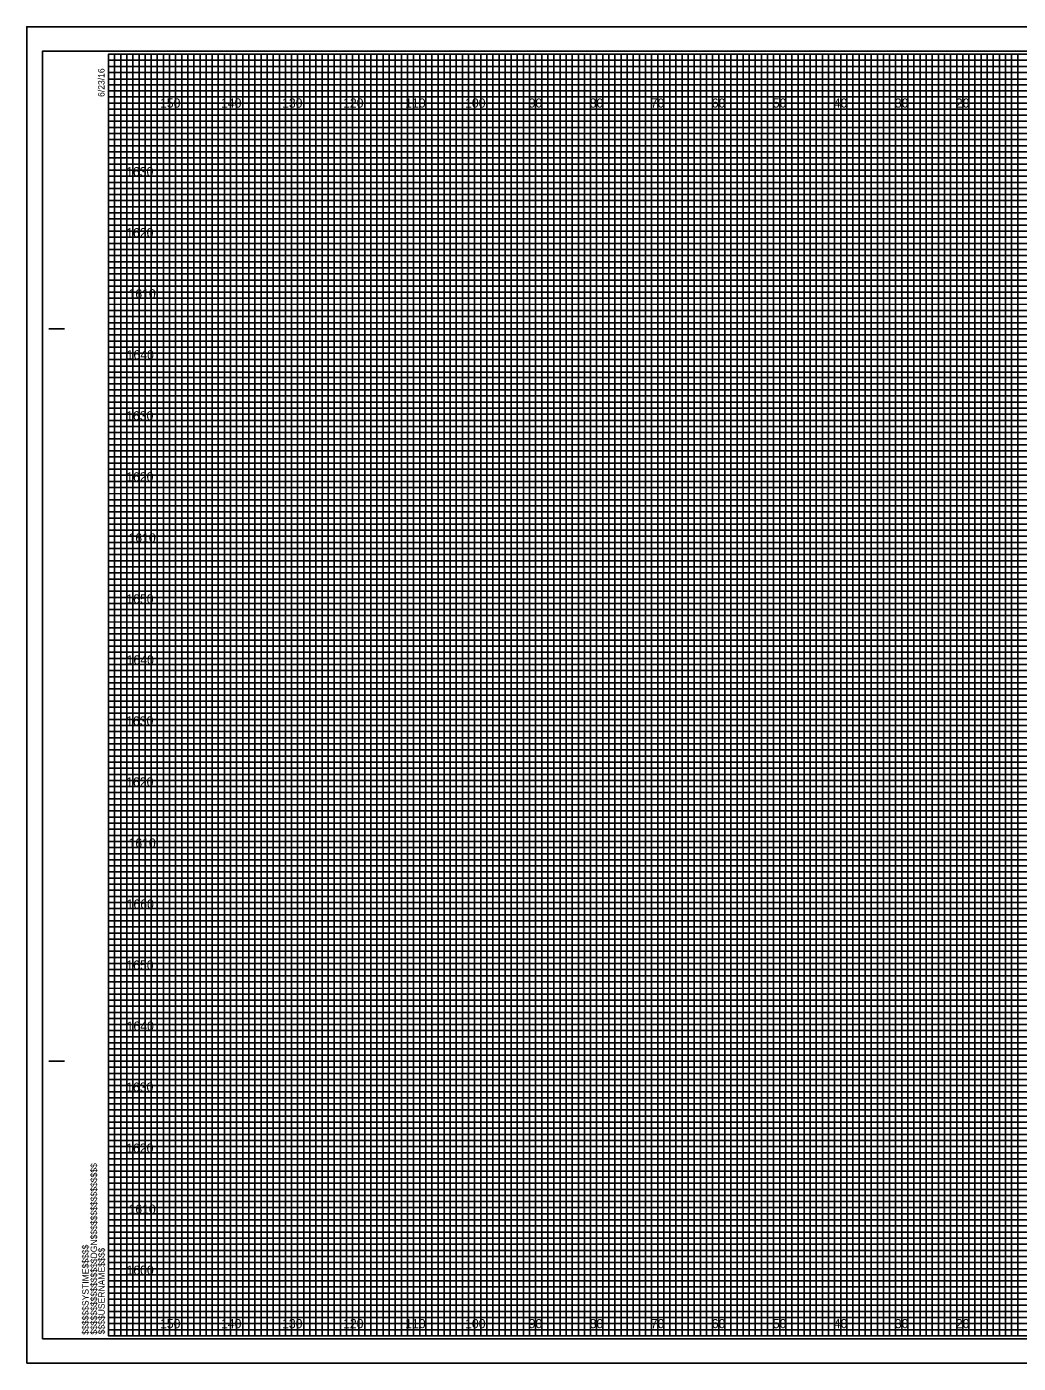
# Model space of a CAD drawing. Extents: x -13 to 323, y -5 to 6154.
# Drawn here: x -13.4 to 149.1, y 5935.5 to 6154.5 of the extents above; entities that cross this region are included whole.
import ezdxf

# ---------------------------------------------------------------- set-up
doc = ezdxf.new("R2010")
doc.units = 0
for name, color, linetype in [('Prop Retaining Wall', 7, 'Continuous'), ('Prop XS Alignment Label', 7, 'Continuous'), ('Prop XS DDE', 7, 'Continuous'), ('Prop XS DDE Elevations', 7, 'Continuous'), ('Prop XS DDE Slope Text', 7, 'Continuous'), ('Prop XS Earthwork Shape', 7, 'Continuous'), ('Prop XS Elevation Labels', 7, 'Continuous'), ('Prop XS Station Labels', 7, 'Continuous'), ('Raster_Level_0', 7, 'Continuous'), ('Scratch_Level_3', 7, 'Continuous'), ('Sheet Cutting Line CELL', 7, 'Continuous')]:
    doc.layers.add(name, color=color, linetype=linetype)

msp = doc.modelspace()

# ---------------------------------------------------------------- linework, layer by layer
at = {"layer": 'Prop Retaining Wall'}
for p, q in [((0, 6149), (260, 6149)), ((260, 6147.98), (0, 6147.98)), ((0, 6147.98), (0, 6147)), ((0, 6147), (260, 6147)), ((260, 6145.89), (0, 6145.89)), ((0, 6145.89), (0, 6144)), ((0, 6144), (320, 6144))]:
    msp.add_line(p, q, dxfattribs=at)
for points in [[(0, 6143), (270, 6143), (320, 6143), (320, 6142), (0, 6142)], [(0, 6141), (320, 6141), (320, 6139), (0, 6139)], [(0, 6138), (320, 6138), (320, 6137), (0, 6136.98)], [(0, 6136), (320, 6136), (320, 6134), (0, 6134)], [(0, 6133), (320, 6133), (320, 6132), (0, 6132)], [(0, 6131), (320, 6131), (320, 6129), (0, 6129)], [(0, 6128), (320, 6128), (320, 6127), (0, 6127)], [(0, 6126), (320, 6126), (320, 6124), (0, 6124)], [(0, 6123), (320, 6123), (320, 6122), (0, 6122)], [(0, 6121), (320, 6121), (320, 6119), (0, 6119)], [(0, 6118), (320, 6118), (320, 6117), (0, 6117)], [(0, 6116), (320, 6116), (320, 6113.95), (320, 6113), (320, 6112), (0, 6112)], [(0, 6114), (320, 6114), (320, 6113), (0, 6113)], [(0, 6111), (320, 6111), (320, 6109), (0, 6109.03)], [(0, 6109.03), (320, 6109), (320, 6108), (0, 6108)], [(0, 6107), (320, 6107), (320, 6106), (0, 6106)], [(0, 6104), (320, 6104), (320, 6103), (0, 6103)], [(0, 6102), (320, 6102), (320, 6101), (0, 6101)], [(-0.07, 6098.89), (320, 6098.89), (320, 6097.88), (-0.07, 6097.88)], [(0, 6097), (320, 6097), (320, 6096), (0, 6096)], [(0, 6094), (320, 6094), (320, 6093), (0, 6093)], [(0, 6092), (320, 6092), (320, 6091), (0, 6091)], [(0, 6089), (320, 6089), (320, 6088), (0, 6088)], [(0, 6087), (320, 6087), (320, 6086), (0, 6086)], [(0, 6084), (320, 6084), (320, 6083), (0, 6083)], [(0, 6082), (320, 6082), (320, 6081), (0, 6081)], [(0, 6079), (320, 6079), (319.99, 6077.98), (0, 6078)], [(0, 6077), (320, 6077), (320, 6076), (0, 6076)], [(0, 6074), (320, 6074), (320, 6073), (0, 6073)], [(0, 6072), (320, 6072), (320, 6071), (0, 6071)], [(0, 6069), (320, 6069), (320, 6068), (0, 6068)], [(0, 6067), (320, 6067), (320, 6066), (0, 6066)], [(0, 6064), (320, 6064), (320, 6063), (0, 6063)], [(0, 6062), (320, 6062), (320, 6061), (0, 6061)], [(0, 6059), (320, 6059), (320, 6058), (0, 6058)], [(0, 6056.99), (320.07, 6056.91), (320, 6056), (0, 6056)], [(0, 6054), (320, 6054), (320, 6053), (0, 6053)], [(0, 6052), (320, 6052), (320, 6051), (0, 6051)], [(0, 6049), (320, 6049), (320, 6048), (0, 6048)], [(0, 6047), (320, 6047), (320, 6046), (0, 6046)], [(0, 6044), (320, 6044), (320, 6043), (0, 6043)], [(0, 6042), (320, 6042), (320, 6041), (0, 6041)], [(0, 6039), (320, 6039), (320, 6038), (0, 6038)], [(0, 6037), (320, 6037), (320, 6036), (0, 6036)], [(0, 6034), (320, 6034), (320, 6033), (0, 6033)], [(0, 6032), (320, 6032), (320, 6031), (0, 6031)], [(0, 6029), (320, 6029), (320, 6028), (0, 6028)], [(0, 6027), (320, 6027), (320, 6026), (0, 6026)], [(0, 6024), (320, 6024), (320, 6023), (0, 6023)], [(0, 6022), (320, 6022), (320, 6021), (0, 6021)], [(0, 6019), (320, 6019), (319.99, 6017.98), (0, 6018)], [(0, 6017), (320, 6017), (320, 6016), (0, 6016)], [(0, 6014), (320, 6014), (320, 6013), (0, 6013)], [(0, 6012), (320, 6012), (320, 6011), (0, 6011)], [(0, 6009), (320, 6009), (320, 6008), (0, 6008)], [(0, 6007), (320, 6007), (320, 6006), (0, 6006)], [(0, 6004), (320, 6004), (320, 6003), (0, 6003)], [(0, 6002), (320, 6002), (320, 6001), (0, 6001)], [(0, 5999), (320, 5999), (320, 5998), (0, 5998)], [(0, 5996.99), (320.07, 5996.91), (320, 5996), (0, 5996)], [(0, 5994), (320, 5994), (320, 5993), (0, 5993)], [(0, 5992), (320, 5992), (320, 5991), (0, 5991)], [(0, 5989), (320, 5989), (320, 5988), (0, 5988)], [(0, 5987), (320, 5987), (320, 5986), (0, 5986)], [(0, 5984), (320, 5984), (320, 5983), (0, 5983)], [(0, 5982), (320, 5982), (320, 5981), (0, 5981)], [(0, 5979), (320, 5979), (320, 5978), (0, 5978)], [(0, 5977), (320, 5977), (320, 5976), (0, 5976)], [(0, 5974), (320, 5974), (320, 5973), (0, 5973)], [(0, 5972), (320, 5972), (320, 5971), (0, 5971)], [(0, 5969), (320, 5969), (320, 5968), (0, 5968)], [(0, 5967), (320, 5967), (320, 5966), (0, 5966)], [(0, 5964), (320, 5964), (320, 5963), (0, 5963)], [(0, 5962), (320, 5962), (320, 5961), (0, 5961)], [(0, 5959), (320, 5959), (320, 5958), (0, 5958)], [(0, 5957), (320, 5957), (320, 5956), (0, 5956)], [(0, 5954), (320, 5954), (320, 5953), (0, 5953)], [(0, 5952), (320, 5952), (320, 5951), (0, 5951)], [(0, 5949), (320, 5949), (320, 5948), (0, 5948)], [(0, 5947), (320, 5947), (320, 5946), (0, 5946)], [(0, 5944), (320, 5944), (320, 5943), (0, 5943)], [(0, 5942), (320, 5942), (320, 5941), (0, 5941)]]:
    msp.add_lwpolyline(points, dxfattribs=at)
at = {"layer": 'Prop XS Alignment Label'}
for p, q in [((-9.8, 6105), (-7.3, 6105)), ((-9.7, 6105), (-7.2, 6105)), ((-9.8, 5985), (-7.3, 5985)), ((-9.7, 5985), (-7.2, 5985)), ((0, 5940), (0, 5940)), ((0, 5940), (0, 5940)), ((0, 5940), (0, 5940)), ((0, 5940), (0, 5940)), ((0, 5940), (0, 5940)), ((0, 5940), (0, 5940)), ((0, 5940), (0, 5940))]:
    msp.add_line(p, q, dxfattribs=at)
msp.add_lwpolyline([(320, 6150), (0, 6150), (0, 5940), (320, 5940)], close=True, dxfattribs=at)
at = {"layer": 'Prop XS DDE'}
msp.add_lwpolyline([(-13.4, 5935.5), (323.3, 5935.5), (323.3, 6154.5), (-13.4, 6154.5)], close=True, dxfattribs=at)
at = {"layer": 'Prop XS DDE Elevations'}
for p, q in [((10, 5940), (10, 6150)), ((20, 5940), (20, 6150)), ((30, 5940), (30, 6150)), ((40, 5940), (40, 6150)), ((50, 5940), (50, 6150)), ((60, 5940), (60, 6150)), ((70, 5940), (70, 6150)), ((80, 5940), (80, 6150)), ((90, 5940), (90, 6150)), ((100, 5940), (100, 6150)), ((110, 5940), (110, 6150)), ((120, 5940), (120, 6150)), ((130, 5940), (130, 6150)), ((140, 5940), (140, 6150)), ((0, 6140), (320, 6140)), ((0, 6130), (320, 6130)), ((0, 6120), (320, 6120)), ((0, 6110), (320, 6110)), ((0, 6100), (320, 6100)), ((0, 6090), (320, 6090)), ((0, 6080), (320, 6080)), ((0, 6070), (320, 6070)), ((0, 6060), (320, 6060)), ((0, 6050), (320, 6050)), ((0, 6040), (320, 6040)), ((0, 6030), (320, 6030)), ((0, 6020), (320, 6020)), ((0, 6010), (320, 6010)), ((0, 6000), (320, 6000)), ((0, 5990), (320, 5990)), ((0, 5980), (320, 5980)), ((0, 5970), (320, 5970)), ((0, 5960), (320, 5960)), ((0, 5950), (320, 5950))]:
    msp.add_line(p, q, dxfattribs=at)
at = {"layer": 'Prop XS DDE Slope Text'}
msp.add_lwpolyline([(-10.8, 5939.5), (322.4, 5939.5), (322.4, 6150.5), (-10.8, 6150.5)], close=True, dxfattribs=at)
at = {"layer": 'Prop XS Earthwork Shape'}
for p, q in [((10, 6150), (0, 6150)), ((10, 5940), (10, 6150)), ((30, 6150), (20, 6150)), ((20, 6150), (20, 5940)), ((30, 5940), (30, 6150)), ((50, 6150), (40, 6150)), ((40, 6150), (40, 5940)), ((50, 5940), (50, 6150)), ((70, 6150), (60, 6150)), ((60, 6150), (60, 5940)), ((70, 5940), (70, 6150)), ((90, 6150), (80, 6150)), ((80, 6150), (80, 5940)), ((90, 5940), (90, 6150)), ((110, 6150), (100, 6150)), ((100, 6150), (100, 5940)), ((110, 5940), (110, 6150)), ((130, 6150), (120, 6150)), ((120, 6150), (120, 5940)), ((130, 5940), (130, 6150)), ((150, 6150), (140, 6150)), ((140, 6150), (140, 5940)), ((20, 5940), (10, 5940)), ((40, 5940), (30, 5940)), ((60, 5940), (50, 5940)), ((80, 5940), (70, 5940)), ((100, 5940), (90, 5940)), ((120, 5940), (110, 5940)), ((140, 5940), (130, 5940))]:
    msp.add_line(p, q, dxfattribs=at)
for points in [[(0, 6140), (320, 6140), (320, 6130), (0, 6130)], [(0, 6120), (320, 6120), (320, 6110), (0, 6110)], [(0, 6100), (320, 6100), (320, 6090), (0, 6090)], [(0, 6080), (320, 6080), (320, 6070), (0, 6070)], [(0, 6060), (320, 6060), (320, 6050), (0, 6050)], [(0, 6040), (320, 6040), (320, 6030), (0, 6030)], [(0, 6020), (320, 6020), (320, 6010), (0, 6010)], [(0, 6000), (320, 6000), (320, 5990), (0, 5990)], [(0, 5980), (320, 5980), (320, 5970), (0, 5970)], [(0, 5960), (320, 5960), (320, 5950), (0, 5950)]]:
    msp.add_lwpolyline(points, dxfattribs=at)
at = {"layer": 'Prop XS Elevation Labels'}
for points in [[(0, 5940), (1, 5940), (1, 6150), (2, 6150), (2, 5940)], [(2, 5940), (3, 5940), (3, 6150), (4, 6150), (4, 5940)], [(5, 5940), (6, 5940), (6, 6150), (7, 6150), (7, 5940)], [(7, 5940), (8, 5940), (8, 6150), (9, 6150), (9, 5940)], [(10, 5940), (11, 5940), (11, 6150), (12, 6150), (12, 5940)], [(12, 5940), (13, 5940), (13, 6150), (14, 6150), (14, 5940)], [(15, 5940), (16, 5940), (16, 6150), (17, 6150), (17, 5940)], [(17, 5940), (18, 5940), (18, 6150), (19, 6150), (19, 5940)], [(20, 5940), (21, 5940), (21, 6150), (22, 6150), (22, 5940)], [(22, 5940), (23, 5940), (23, 6150), (24, 6150), (24, 5940)], [(25, 5940), (26, 5940), (26, 6150), (27, 6150), (27, 5940)], [(27, 5940), (28, 5940), (28, 6150), (29, 6150), (29, 5940)], [(30, 5940), (31, 5940), (31, 6150), (32, 6150), (32, 5940)], [(32, 5940), (33, 5940), (33, 6150), (34, 6150), (34, 5940)], [(35, 5940), (36, 5940), (36, 6150), (37, 6150), (37, 5940)], [(37, 5940), (38, 5940), (38, 6150), (39, 6150), (39, 5940)], [(40, 5940), (41, 5940), (41, 6150), (42, 6150), (42, 5940)], [(42, 5940), (43, 5940), (43, 6150), (44, 6150), (44, 5940)], [(45, 5940), (46, 5940), (46, 6150), (47, 6150), (47, 5940)], [(47, 5940), (48, 5940), (48, 6150), (49, 6150), (49, 5940)], [(50, 5940), (51, 5940), (51, 6150), (52, 6150), (52, 5940)], [(52, 5940), (53, 5940), (53, 6150), (54, 6150), (54, 5940)], [(55, 5940), (56, 5940), (56, 6150), (57, 6150), (57, 5940)], [(57, 5940), (58, 5940), (58, 6150), (59, 6150), (59, 5940)], [(60, 5940), (61, 5940), (61, 6150), (62, 6150), (62, 5940)], [(62, 5940), (63, 5940), (63, 6150), (64, 6150), (64, 5940)], [(65, 5940), (66, 5940), (66, 6150), (67, 6150), (67, 5940)], [(67, 5940), (68, 5940), (68, 6150), (69, 6150), (69, 5940)], [(70, 5940), (71, 5940), (71, 6150), (72, 6150), (72, 5940)], [(72, 5940), (73, 5940), (73, 6150), (74, 6150), (74, 5940)], [(75, 5940), (76, 5940), (76, 6150), (77, 6150), (77, 5940)], [(77, 5940), (78, 5940), (78, 6150), (79, 6150), (79, 5940)], [(80, 5940), (81, 5940), (81, 6150), (82, 6150), (82, 5940)], [(82, 5940), (83, 5940), (83, 6150), (84, 6150), (84, 5940)], [(85, 5940), (86, 5940), (86, 6150), (87, 6150), (87, 5940)], [(87, 5940), (88, 5940), (88, 6150), (89, 6150), (89, 5940)], [(90, 5940), (91, 5940), (91, 6150), (92, 6150), (92, 5940)], [(92, 5940), (93, 5940), (93, 6150), (94, 6150), (94, 5940)], [(95, 5940), (96, 5940), (96, 6150), (97, 6150), (97, 5940)], [(97, 5940), (98, 5940), (98, 6150), (99, 6150), (99, 5940)], [(100, 5940), (101, 5940), (101, 6150), (102, 6150), (102, 5940)], [(102, 5940), (103, 5940), (103, 6150), (104, 6150), (104, 5940)], [(105, 5940), (106, 5940), (106, 6150), (107, 6150), (107, 5940)], [(107, 5940), (108, 5940), (108, 6150), (109, 6150), (109, 5940)], [(110, 5940), (111, 5940), (111, 6150), (112, 6150), (112, 5940)], [(112, 5940), (113, 5940), (113, 6150), (114, 6150), (114, 5940)], [(115, 5940), (116, 5940), (116, 6150), (117, 6150), (117, 5940)], [(117, 5940), (118, 5940), (118, 6150), (119, 6150), (119, 5940)], [(120, 5940), (121, 5940), (121, 6150), (122, 6150), (122, 5940)], [(122, 5940), (123, 5940), (123, 6150), (124, 6150), (124, 5940)], [(125, 5940), (126, 5940), (126, 6150), (127, 6150), (127, 5940)], [(127, 5940), (128, 5940), (128, 6150), (129, 6150), (129, 5940)], [(130, 5940), (131, 5940), (131, 6150), (132, 6150), (132, 5940)], [(132, 5940), (133, 5940), (133, 6150), (134, 6150), (134, 5940)], [(135, 5940), (136, 5940), (136, 6150), (137, 6150), (137, 5940)], [(137, 5940), (138, 5940), (138, 6150), (139, 6150), (139, 5940)], [(140, 5940), (141, 5940), (141, 6150), (142, 6150), (142, 5940)], [(142, 5940), (143, 5940), (143, 6150), (144, 6150), (144, 5940)], [(145, 5940), (146, 5940), (146, 6150), (147, 6150), (147, 5940)], [(147, 5940), (148, 5940), (148, 6150), (149, 6150), (149, 5940)]]:
    msp.add_lwpolyline(points, dxfattribs=at)
at = {"layer": 'Prop XS Station Labels'}
for points in [[(0, 6150), (5, 6150), (5, 5940), (15, 5940), (15, 6150), (25, 6150), (25, 5940), (35, 5940), (35, 6150), (45, 6150), (45, 5940), (55, 5940), (55, 6150), (65, 6150), (65, 5940), (75, 5940), (75, 6150), (85, 6150), (85, 5940), (95, 5940), (95, 6150), (105, 6150), (105, 5940), (115, 5940), (115, 6150), (125, 6150), (125, 5940), (135, 5940), (135, 6150), (145, 6150), (145, 5940), (155, 5940)], [(0, 6145), (275, 6145)], [(0, 6125), (320, 6125), (320, 6135), (0, 6135)], [(0, 6105), (320, 6105), (320, 6115), (0, 6115)], [(0, 6085), (320, 6085), (320, 6095), (0, 6095)], [(0, 6065), (320, 6065), (320, 6075), (0, 6075)], [(0, 6045), (320, 6045), (320, 6055), (0, 6055)], [(0, 6025), (320, 6025), (320, 6035), (0, 6035)], [(0, 6005), (320, 6005), (320, 6015), (0, 6015)], [(0, 5985), (320, 5985), (320, 5995), (0, 5995)], [(0, 5965), (320, 5965), (320, 5975), (0, 5975)], [(0, 5945), (320, 5945), (320, 5955), (0, 5955)]]:
    msp.add_lwpolyline(points, dxfattribs=at)
at = {"layer": 'Sheet Cutting Line CELL'}
for p, q in [((323.3, 6154.5), (-13.4, 6154.5)), ((-13.4, 6154.5), (-13.4, 5935.5)), ((-13.4, 5935.5), (323.3, 5935.5))]:
    msp.add_line(p, q, dxfattribs=at)

# ---------------------------------------------------------------- texts
at = {"layer": 'Prop XS Alignment Label'}
for s, p in [('6/23/16', (-0.65, 6143)), ('$$$$$$$$$$$$$$$$DGN$$$$$$$$$$$$$$$$', (-1.88, 5940.18)), ('$$$$$$SYSTIME$$$$$', (-3.26, 5940.18)), ('$$$$USERNAME$$$$', (-0.62, 5940.23))]:
    msp.add_text(s, height=1.05, rotation=90, dxfattribs=at).set_placement(p)
at = {"layer": 'Raster_Level_0'}
for s, p in [('150', (8.44, 6141.25)), ('140', (18.44, 6141.25)), ('130', (28.44, 6141.25)), ('120', (38.44, 6141.25)), ('110', (48.62, 6141.25)), ('100', (58.44, 6141.25)), ('90', (68.86, 6141.25)), ('80', (78.86, 6141.25)), ('70', (88.86, 6141.25)), ('60', (98.86, 6141.25)), ('50', (108.86, 6141.25)), ('40', (118.86, 6141.25)), ('30', (128.86, 6141.25)), ('20', (138.86, 6141.25)), ('150', (8.44, 5941.25)), ('140', (18.44, 5941.25)), ('130', (28.44, 5941.25)), ('120', (38.44, 5941.25)), ('110', (48.62, 5941.25)), ('100', (58.44, 5941.25)), ('90', (68.86, 5941.25)), ('80', (78.86, 5941.25)), ('70', (88.86, 5941.25)), ('60', (98.86, 5941.25)), ('50', (108.86, 5941.25)), ('40', (118.86, 5941.25)), ('30', (128.86, 5941.25)), ('20', (138.86, 5941.25))]:
    msp.add_text(s, height=1.5, dxfattribs=at).set_placement(p)
at = {"layer": 'Scratch_Level_3'}
for s, p in [('1630', (2.89, 6130)), ('1620', (2.9, 6120)), ('1610', (3.28, 6110)), ('1640', (2.97, 6100)), ('1630', (2.89, 6090)), ('1620', (2.9, 6080)), ('1610', (3.28, 6070)), ('1650', (2.92, 6060)), ('1640', (2.97, 6050)), ('1630', (2.89, 6040)), ('1620', (2.9, 6030)), ('1610', (3.28, 6020)), ('1660', (2.97, 6010)), ('1650', (2.92, 6000)), ('1640', (2.97, 5990)), ('1630', (2.89, 5980)), ('1620', (2.9, 5970)), ('1610', (3.28, 5960)), ('1600', (2.95, 5950))]:
    msp.add_text(s, height=1.5, dxfattribs=at).set_placement(p)

doc.saveas('drawing.dxf')
